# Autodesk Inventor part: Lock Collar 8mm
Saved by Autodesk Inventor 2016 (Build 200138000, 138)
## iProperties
Created: 2015-11
Part Number: Lock Collar 8mm
Material: Generic
Document SubType Name: Modeling
Designer: John
Density: 1 g/cm^3
Appearance: Default
Author: John
Revision Number: ANY
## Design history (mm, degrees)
feature "M5x0.8 Tapped Hole1"
body "Solid1"
